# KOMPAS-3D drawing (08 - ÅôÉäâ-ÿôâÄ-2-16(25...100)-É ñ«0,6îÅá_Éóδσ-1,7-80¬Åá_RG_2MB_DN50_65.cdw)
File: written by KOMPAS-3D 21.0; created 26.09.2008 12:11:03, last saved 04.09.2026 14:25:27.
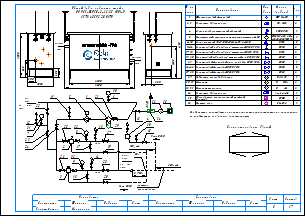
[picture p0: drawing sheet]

Sheets 1-2: A3, landscape

Document properties: Наименование: Макро:21; Автор: RaskoAdmin; Форматы листов документа: 2xA3; Полное имя файла: \\ur38nt01\Departments\КТО\КБ ПУРДГ\Заявки\Прайс-лист на типовые шкафы ГРПШ\ПУРДГ_стандарт_30_04_2026\ПУРДГ с RG_2MB\ПУРДГ-ШУГО-2-16(25...100)-Р до0,6МПа_Рвых-1,7-80кПа_RG_2MB_DN50_65.cdw

Title block, sheet 1: Наименование: Пункт учета газа / ПУГ-Ш-400-Р / ЛГТИ.485922.001ТУ; designation: ЛГТИ.03.4411141; sheet number: 1; Количество листов документа: 2; organisation: ООО "ЭЛЬСТЕР Газэлектроника"; Форматы листов документа: A3; stored path: C:\Рабочие документы\Компас\ПУГ\Схема.cdw; Разработал: Устинов; Проверил: Кошкин; Утвердил: Кошкин
Title block, sheet 2: sheet number: 2; stored path: D:\Рабочие документы\Заявки\ПУРДГ\ПУРДГ-ШУЭО-2-100-Р 4411220.cdw; designation, second copy: ЛГТИ.03.4411141-

Views: Вид 1, Вид 2
Referenced files: wcvoit.frw
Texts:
  Normal
  № на
  схеме
  Усл.
  обозн.
  Марка
  (модель)
  Кол.
  Фильтр газовый фланцевый
  ФГ 16-50
  Регулятор давления газа
  RG/2MB
  Клапан предохранительный сбросной
  КПС DN20
  Измерительный комплекс с ротационным счетчиком Ду50
  СГ-ЭК-Р-(0,2...2,0)-
  Кран кнопочный VE-РАСКО-НЗ-1,6-G1/2-М20
  DN15
  Кран шаровой "под приварку" штуцерный DN20 PN16
  DN20
  Кран шаровой "под приварку" штуцерный DN15 PN16
  Кран шаровой "под приварку" штуцерный п/п DN20 PN16
  Кран шаровой фланцевый с мех. приводом DN50 PN16
  Кран шаровой фланцевый DN50 PN16
  Кран шаровой фланцевый DN65 PN16
  DN50
  DN65
  Индикатор перепада давления
  Манометр
  Манометр-напоромер
  Обогреватель газогорелочный шкафной
  (Эльтон")
  Счетчик газа
  Delta 15
  0...     МПа
  0...     кПа
  Venio-A-15
  ОГШН
  BK-G1,6
  Общий вид и габариты шкафа
  ПУРДГ-ШУГО-2-16(25...100)-Р
  Выход газа
  Вход газа
  logo-rasko-ge.png
  DN 1
  местное
  сопротивление
  Римп DN20
  Выход
  газа
  Р=     кПа
  Вход
  Р=       МПа
  PDI
  Схема открывания дверей
  Предприятие изготовитель может заменять комплектующие на аналогичные,
  не ухудшающие заявленных характеристик.
  Должность
  Конструктор
  Фамилия
  Подпись
  Дата
  Согласовано
  Максимкин
  Лист
  Листов
  POLYLINE_STYLE_0.18_RGB_0_0_0
  POLYLINE_STYLE_0.50_RGB_0_0_0
  POLYLINE_STYLE_0.34_RGB_0_0_0
  PHANTOM_RGB_0_0_0_SC_1_THICK_0.18
  K5LT_THIN_RGB_0_0_0_THICK_0.18
  K5LT32769_RGB_0_0_0_THICK_0.18
  K5LT12_RGB_0_0_0_SC_1_THICK_0.18
  K5LT_DASHED_RGB_0_0_0_SC_1_THICK_0.18
  ACISOTGL_RGB_0_0_0_SC_0.8_THICK_0.25
  CONTINUOUS_RGB_0_127_31_THICK_0.3
  CONTINUOUS_RGB_0_0_255_THICK_0.35
  CONTINUOUS_RGB_255_0_0_THICK_0.35
  POLYLINE_STYLE_0.25_RGB_0_0_0
  CONTINUOUS_RGB_0_0_0_THICK_0.5
  POLYLINE_STYLE_0.35_RGB_0_0_255
  CONTINUOUS_RGB_0_0_0_THICK_0.4
  CONTINUOUS_RGB_0_0_0_THICK_0.35
  НЕВИДИМАЯ_RGB_0_0_0_SC_0.3_THICK_0.25
  СONTINUOUS_RGB_0_0_0_THICK_0.25
  ОСЕВАЯ2_RGB_248_153_30_SC_0.3_THICK_0.25
  Без оформления
Dimensions and other numbers on the sheet: 1; 2, 3; 2; 4; 5; 6-10; 11-16; 6; 17, 18; 19, 20; 21; 22-26; 27, 28; 29; 30, 31; 32, 33; 34; 35; 36; 1500; 250; 300; 1050; 550; 305; 2300; 4130; 2000; 2600; 5,,,7DN 1; 7; 31; 12; 22; 23; 24; 11; 30; 25; 32; 8; 17; 13; 27; 19; 10; 15; 26; 33; 9; 3; 18; 14; 28; 20; 16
